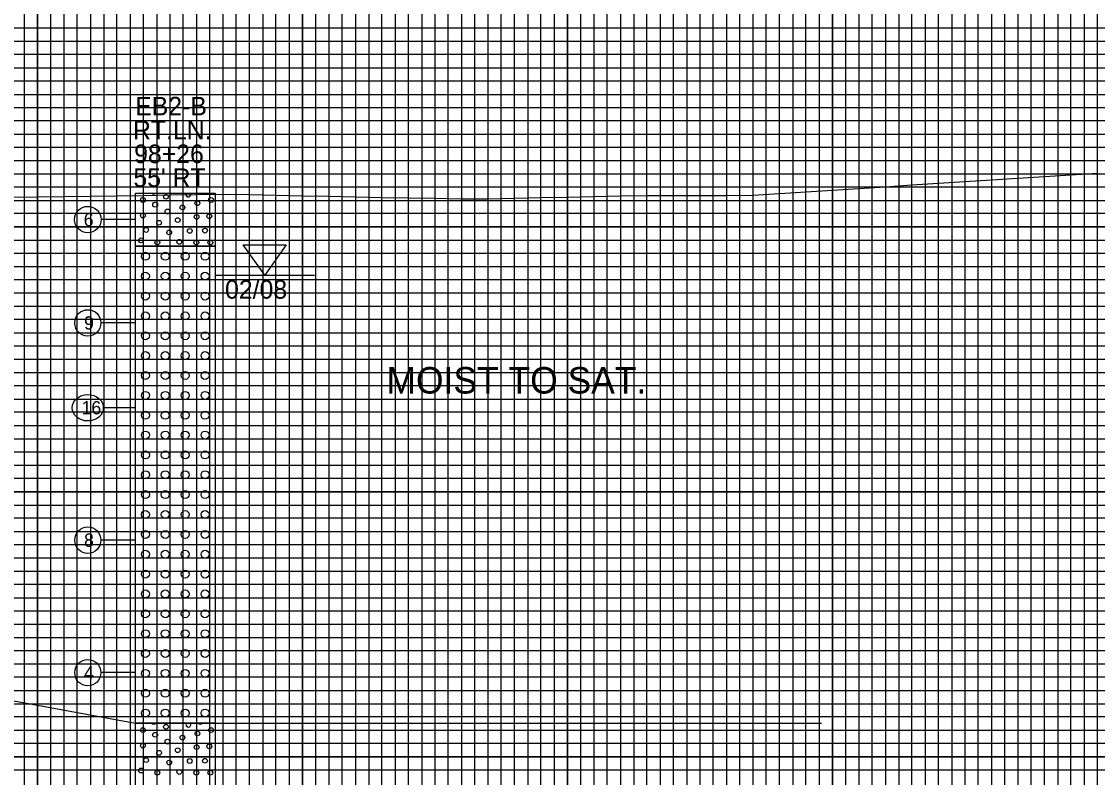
# Model space of a CAD drawing. Extents: x 2345490 to 2436403, y 465165 to 573888.
# Drawn here: x 2396213.5 to 2396619.5, y 557776.3 to 558061.6 of the extents above; entities that cross this region are included whole.
import ezdxf

# ---------------------------------------------------------------- set-up
doc = ezdxf.new("R2010")
doc.units = 0
for name, color, linetype in [('Old_Level_1', 7, 'Continuous'), ('Prop Road Sect_ Boring - Header Labels from Geopak', 7, 'Continuous'), ('Prop Road Sect_ Boring - Material (Outline)', 7, 'Continuous'), ('Prop Road Sect_ Boring - Peripheral (24 Hr GrdWtr Date)', 7, 'Continuous'), ('Prop Road Sect_ Boring - Peripheral (SPT Oval + Leader)', 7, 'Continuous'), ('Prop Road Sect_ Boring - Peripheral (SPT Tx)', 7, 'Continuous'), ('Prop Strc Sect_ Material - Contact (General - Minor)', 7, 'Continuous'), ('Prop Strc Sect_ Material - Tx (Composite Desc)', 7, 'Continuous'), ('Sheet DOT Grid CELL', 7, 'Continuous'), ('Sheet Profile Grid Major CELL', 7, 'Continuous'), ('Sheet Profile Grid Middle CELL', 7, 'Continuous'), ('Sheet Profile Grid Minor CELL', 7, 'Continuous'), ('Water Mark (24 Hr) Cell', 7, 'Continuous')]:
    doc.layers.add(name, color=color, linetype=linetype)

msp = doc.modelspace()

# ---------------------------------------------------------------- linework, layer by layer
at = {"layer": 'Old_Level_1'}
msp.add_lwpolyline([(2396209.54964, 557995.361), (2396219.54964, 557995.45925), (2396229.54964, 557995.5575), (2396239.54964, 557995.67625), (2396249.54964, 557995.834), (2396259.54964, 557995.9915), (2396269.54964, 557996.14925), (2396279.54964, 557996.30675), (2396289.54964, 557996.46425), (2396299.54964, 557996.27275), (2396309.54964, 557996.08875), (2396319.54964, 557995.85825), (2396329.54964, 557995.62925), (2396339.54964, 557995.4), (2396349.54964, 557995.2215), (2396359.54964, 557995.04825), (2396369.54964, 557994.875), (2396379.54964, 557994.70175), (2396389.54964, 557994.733), (2396399.54964, 557994.94025), (2396409.54964, 557995.1475), (2396419.54964, 557995.35475), (2396429.54964, 557995.562), (2396439.54964, 557995.76925), (2396449.54964, 557995.9055), (2396459.54964, 557995.93625), (2396469.54964, 557995.967), (2396479.54964, 557996.00175), (2396489.54964, 557996.0785), (2396499.54964, 557996.666), (2396509.54964, 557997.31575), (2396519.54964, 557997.9655), (2396529.54964, 557998.6155), (2396539.54964, 557999.26525), (2396549.54964, 557999.915), (2396559.54964, 558000.5645), (2396569.54964, 558001.192), (2396579.54964, 558001.89575), (2396589.54964, 558002.502), (2396599.54964, 558003.10825), (2396609.54964, 558003.714), (2396619.54964, 558004.3195)], dxfattribs=at)
at = {"layer": 'Prop Road Sect_ Boring - Material (Outline)'}
for points in [[(2396256.54964, 557996.83938), (2396286.54964, 557996.83938), (2396286.54964, 557976.83938), (2396256.54964, 557976.83938)], [(2396256.54964, 557976.83938), (2396286.54964, 557976.83938), (2396286.54964, 557796.83938), (2396256.54964, 557796.83938)], [(2396256.54964, 557796.83938), (2396286.54964, 557796.83938), (2396286.54964, 557596.83938), (2396256.54964, 557596.83938)]]:
    msp.add_lwpolyline(points, close=True, dxfattribs=at)
for centre, radius in [((2396268.0427, 557995.47573), 0.9), ((2396259.34269, 557994.24573), 0.9), ((2396263.9627, 557992.47573), 0.9), ((2396274.25272, 557991.44072), 0.9), ((2396279.89273, 557993.01573), 0.9), ((2396285.06774, 557994.24573), 0.9), ((2396259.34269, 557988.39572), 0.9), ((2396268.6127, 557989.89572), 0.9), ((2396279.62273, 557987.84072), 0.9), ((2396284.39274, 557988.12572), 0.9), ((2396260.55769, 557982.93571), 0.9), ((2396265.4627, 557985.66571), 0.9), ((2396272.48271, 557986.65571), 0.9), ((2396258.65268, 557979.0057), 0.9), ((2396269.27271, 557981.9907), 0.9), ((2396277.02772, 557982.59071), 0.9), ((2396282.75773, 557982.68071), 0.9), ((2396264.7727, 557978.1807), 0.9), ((2396273.08271, 557978.4507), 0.9), ((2396279.48773, 557978.1807), 0.9), ((2396284.79774, 557978.1807), 0.9), ((2396260.28653, 557972.99104), 1.5), ((2396267.78653, 557972.99104), 1.5), ((2396275.28653, 557972.99104), 1.5), ((2396282.78653, 557972.99104), 1.5), ((2396260.28653, 557965.49104), 1.5), ((2396267.78653, 557965.49104), 1.5), ((2396275.28653, 557965.49104), 1.5), ((2396282.78653, 557965.49104), 1.5), ((2396260.28653, 557957.99104), 1.5), ((2396267.78653, 557957.99104), 1.5), ((2396275.28653, 557957.99104), 1.5), ((2396282.78653, 557957.99104), 1.5), ((2396260.28653, 557950.49104), 1.5), ((2396267.78653, 557950.49104), 1.5), ((2396275.28653, 557950.49104), 1.5), ((2396282.78653, 557950.49104), 1.5), ((2396260.28653, 557943.00604), 1.5), ((2396267.78653, 557943.00604), 1.5), ((2396275.28653, 557943.00604), 1.5), ((2396282.78653, 557943.00604), 1.5), ((2396260.28653, 557935.50604), 1.5), ((2396267.78653, 557935.50604), 1.5), ((2396275.28653, 557935.50604), 1.5), ((2396282.78653, 557935.50604), 1.5), ((2396260.28653, 557928.00604), 1.5), ((2396267.78653, 557928.00604), 1.5), ((2396275.28653, 557928.00604), 1.5), ((2396282.78653, 557928.00604), 1.5), ((2396260.28653, 557920.50604), 1.5), ((2396267.78653, 557920.50604), 1.5), ((2396275.28653, 557920.50604), 1.5), ((2396282.78653, 557920.50604), 1.5), ((2396260.28653, 557913.02104), 1.5), ((2396267.78653, 557913.02104), 1.5), ((2396275.28653, 557913.02104), 1.5), ((2396282.78653, 557913.02104), 1.5), ((2396260.28653, 557905.52104), 1.5), ((2396267.78653, 557905.52104), 1.5), ((2396275.28653, 557905.52104), 1.5), ((2396282.78653, 557905.52104), 1.5), ((2396260.28653, 557898.02104), 1.5), ((2396267.78653, 557898.02104), 1.5), ((2396275.28653, 557898.02104), 1.5), ((2396282.78653, 557898.02104), 1.5), ((2396260.28653, 557890.52104), 1.5), ((2396267.78653, 557890.52104), 1.5), ((2396275.28653, 557890.52104), 1.5), ((2396282.78653, 557890.52104), 1.5), ((2396260.28653, 557883.03604), 1.5), ((2396267.78653, 557883.03604), 1.5), ((2396275.28653, 557883.03604), 1.5), ((2396282.78653, 557883.03604), 1.5), ((2396260.28653, 557875.53604), 1.5), ((2396267.78653, 557875.53604), 1.5), ((2396275.28653, 557875.53604), 1.5), ((2396282.78653, 557875.53604), 1.5), ((2396260.28653, 557868.03604), 1.5), ((2396267.78653, 557868.03604), 1.5), ((2396275.28653, 557868.03604), 1.5), ((2396282.78653, 557868.03604), 1.5), ((2396260.28653, 557860.53604), 1.5), ((2396267.78653, 557860.53604), 1.5), ((2396275.28653, 557860.53604), 1.5), ((2396282.78653, 557860.53604), 1.5), ((2396260.28653, 557853.05104), 1.5), ((2396267.78653, 557853.05104), 1.5), ((2396275.28653, 557853.05104), 1.5), ((2396282.78653, 557853.05104), 1.5), ((2396260.28653, 557845.55104), 1.5), ((2396267.78653, 557845.55104), 1.5), ((2396275.28653, 557845.55104), 1.5), ((2396282.78653, 557845.55104), 1.5), ((2396260.28653, 557838.05104), 1.5), ((2396267.78653, 557838.05104), 1.5), ((2396275.28653, 557838.05104), 1.5), ((2396282.78653, 557838.05104), 1.5), ((2396260.28653, 557830.55104), 1.5), ((2396267.78653, 557830.55104), 1.5), ((2396275.28653, 557830.55104), 1.5), ((2396282.78653, 557830.55104), 1.5), ((2396260.28653, 557823.06604), 1.5), ((2396267.78653, 557823.06604), 1.5), ((2396275.28653, 557823.06604), 1.5), ((2396282.78653, 557823.06604), 1.5), ((2396260.28653, 557815.56604), 1.5), ((2396267.78653, 557815.56604), 1.5), ((2396275.28653, 557815.56604), 1.5), ((2396282.78653, 557815.56604), 1.5), ((2396260.28653, 557808.06604), 1.5), ((2396267.78653, 557808.06604), 1.5), ((2396275.28653, 557808.06604), 1.5), ((2396282.78653, 557808.06604), 1.5), ((2396260.28653, 557800.56604), 1.5), ((2396267.78653, 557800.56604), 1.5), ((2396275.28653, 557800.56604), 1.5), ((2396282.78653, 557800.56604), 1.5), ((2396259.34269, 557794.15573), 0.9), ((2396263.9627, 557792.38573), 0.9), ((2396268.0427, 557795.38573), 0.9), ((2396279.89273, 557792.92573), 0.9), ((2396285.06774, 557794.15573), 0.9), ((2396259.34269, 557788.30572), 0.9), ((2396268.6127, 557789.80572), 0.9), ((2396274.25272, 557791.35072), 0.9), ((2396284.39274, 557788.03572), 0.9), ((2396265.4627, 557785.57571), 0.9), ((2396272.48271, 557786.56571), 0.9), ((2396279.62273, 557787.75072), 0.9), ((2396260.55769, 557782.84571), 0.9), ((2396269.27271, 557781.9007), 0.9), ((2396277.02772, 557782.50071), 0.9), ((2396282.75773, 557782.59071), 0.9), ((2396258.65268, 557778.9157), 0.9), ((2396264.7727, 557778.0907), 0.9), ((2396273.08271, 557778.3607), 0.9), ((2396279.48773, 557778.0907), 0.9), ((2396284.79774, 557778.0907), 0.9)]:
    msp.add_circle(centre, radius, dxfattribs=at)
for centre, start, end in [((2396263.42269, 557997.38074), 216.9781555, 323.0218445), ((2396276.48772, 557996.28573), 142.0367311, 37.9632689), ((2396280.98773, 557997.38074), 216.9781555, 323.0218445), ((2396263.42269, 557797.29074), 210.0999971, 329.9000029), ((2396276.48772, 557796.19573), 134.3440169, 45.6559831), ((2396280.98773, 557797.29074), 210.0999971, 329.9000029)]:
    msp.add_arc(centre, 0.9, start, end, dxfattribs=at)
at = {"layer": 'Prop Road Sect_ Boring - Peripheral (SPT Oval + Leader)'}
for p, q in [((2396256.54964, 557986.83938), (2396243.58507, 557986.83938)), ((2396256.54964, 557947.83938), (2396243.46696, 557947.83938)), ((2396256.54964, 557915.83938), (2396244.41184, 557915.83938)), ((2396256.54964, 557865.83938), (2396243.46696, 557865.83938)), ((2396256.54964, 557815.83938), (2396243.46696, 557815.83938))]:
    msp.add_line(p, q, dxfattribs=at)
for centre, major_axis, ratio in [((2396238.54964, 557986.83938), (5.03543, 0), 0.992963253), ((2396238.54964, 557947.83938), (0, 5), 0.983464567), ((2396238.54964, 557915.83938), (5.8622, 0), 0.852921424), ((2396238.54964, 557865.83938), (0, 5), 0.983464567), ((2396238.54964, 557815.83938), (0, 5), 0.983464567)]:
    msp.add_ellipse(centre, major_axis=major_axis, ratio=ratio, dxfattribs=at)
at = {"layer": 'Prop Strc Sect_ Material - Contact (General - Minor)'}
for p, q in [((2395988.54964, 557845.85303), (2396256.54964, 557796.83938)), ((2396286.54964, 557796.83938), (2396515.3748, 557796.83938))]:
    msp.add_line(p, q, dxfattribs=at)
at = {"layer": 'Sheet DOT Grid CELL'}
for p, q in [((2396219.54994, 558259.113), (2396219.54994, 557234.113)), ((2396269.54994, 558259.113), (2396269.54994, 557234.113)), ((2396319.54994, 558259.113), (2396319.54994, 557234.113)), ((2396369.54994, 558259.113), (2396369.54994, 557234.113)), ((2396419.54994, 558259.113), (2396419.54994, 557234.113)), ((2396469.54994, 558259.113), (2396469.54994, 557234.113)), ((2396519.54994, 558259.113), (2396519.54994, 557234.113)), ((2396569.54994, 558259.113), (2396569.54994, 557234.113)), ((2395319.54994, 558034.113), (2396819.54994, 558034.113)), ((2395319.54994, 557984.113), (2396819.54994, 557984.113)), ((2395319.54994, 557934.113), (2396819.54994, 557934.113)), ((2395319.54994, 557884.113), (2396819.54994, 557884.113)), ((2395319.54994, 557834.113), (2396819.54994, 557834.113)), ((2395319.54994, 557784.113), (2396819.54994, 557784.113))]:
    msp.add_line(p, q, dxfattribs=at)
at = {"layer": 'Sheet Profile Grid Major CELL'}
for points in [[(2396169.54994, 557234.113), (2396219.54994, 557234.113), (2396219.54994, 558259.113), (2396269.54994, 558259.113), (2396269.54994, 557234.113), (2396319.54994, 557234.113), (2396319.54994, 558259.113), (2396369.54994, 558259.113), (2396369.54994, 557234.113), (2396419.54994, 557234.113), (2396419.54994, 558259.113), (2396469.54994, 558259.113), (2396469.54994, 557234.113), (2396519.54994, 557234.113), (2396519.54994, 558259.113), (2396569.54994, 558259.113), (2396569.54994, 557234.113), (2396619.54994, 557234.113), (2396619.54994, 558259.113), (2396645.84994, 558259.113)], [(2396819.54994, 557984.113), (2395319.54994, 557984.113), (2395319.54994, 558034.113), (2396819.54994, 558034.113)], [(2396819.54994, 557884.113), (2395319.54994, 557884.113), (2395319.54994, 557934.113), (2396819.54994, 557934.113)], [(2396819.54994, 557784.113), (2395319.54994, 557784.113), (2395319.54994, 557834.113), (2396819.54994, 557834.113)]]:
    msp.add_lwpolyline(points, dxfattribs=at)
at = {"layer": 'Sheet Profile Grid Middle CELL'}
for points in [[(2396194.54994, 558259.113), (2396244.54994, 558259.113), (2396244.54994, 557234.113), (2396294.54994, 557234.113), (2396294.54994, 558259.113), (2396344.54994, 558259.113), (2396344.54994, 557234.113), (2396394.54994, 557234.113), (2396394.54994, 558259.113), (2396444.54994, 558259.113), (2396444.54994, 557234.113), (2396494.54994, 557234.113), (2396494.54994, 558259.113), (2396544.54994, 558259.113), (2396544.54994, 557234.113), (2396594.54994, 557234.113), (2396594.54994, 558259.113)], [(2396819.54994, 558059.113), (2395319.54994, 558059.113), (2395319.54994, 558009.113), (2396819.54994, 558009.113)], [(2396819.54994, 557959.113), (2395319.54994, 557959.113), (2395319.54994, 557909.113), (2396819.54994, 557909.113)], [(2396819.54994, 557859.113), (2395319.54994, 557859.113), (2395319.54994, 557809.113), (2396819.54994, 557809.113)]]:
    msp.add_lwpolyline(points, dxfattribs=at)
at = {"layer": 'Sheet Profile Grid Minor CELL'}
msp.add_line((2396769.54994, 558054.113), (2395369.54994, 558054.113), dxfattribs=at)
for points in [[(2396209.54994, 558259.113), (2396214.54994, 558259.113), (2396214.54994, 557234.113)], [(2396224.54994, 557234.113), (2396224.54994, 558259.113), (2396229.54994, 558259.113), (2396229.54994, 557234.113)], [(2396234.54994, 557234.113), (2396234.54994, 558259.113), (2396239.54994, 558259.113), (2396239.54994, 557234.113)], [(2396249.54994, 557234.113), (2396249.54994, 558259.113), (2396254.54994, 558259.113), (2396254.54994, 557234.113)], [(2396259.54994, 557234.113), (2396259.54994, 558259.113), (2396264.54994, 558259.113), (2396264.54994, 557234.113)], [(2396274.54994, 557234.113), (2396274.54994, 558259.113), (2396279.54994, 558259.113), (2396279.54994, 557234.113)], [(2396284.54994, 557234.113), (2396284.54994, 558259.113), (2396289.54994, 558259.113), (2396289.54994, 557234.113)], [(2396299.54994, 557234.113), (2396299.54994, 558259.113), (2396304.54994, 558259.113), (2396304.54994, 557234.113)], [(2396309.54994, 557234.113), (2396309.54994, 558259.113), (2396314.54994, 558259.113), (2396314.54994, 557234.113)], [(2396324.54994, 557234.113), (2396324.54994, 558259.113), (2396329.54994, 558259.113), (2396329.54994, 557234.113)], [(2396334.54994, 557234.113), (2396334.54994, 558259.113), (2396339.54994, 558259.113), (2396339.54994, 557234.113)], [(2396349.54994, 557234.113), (2396349.54994, 558259.113), (2396354.54994, 558259.113), (2396354.54994, 557234.113)], [(2396359.54994, 557234.113), (2396359.54994, 558259.113), (2396364.54994, 558259.113), (2396364.54994, 557234.113)], [(2396374.54994, 557234.113), (2396374.54994, 558259.113), (2396379.54994, 558259.113), (2396379.54994, 557234.113)], [(2396384.54994, 557234.113), (2396384.54994, 558259.113), (2396389.54994, 558259.113), (2396389.54994, 557234.113)], [(2396399.54994, 557234.113), (2396399.54994, 558259.113), (2396404.54994, 558259.113), (2396404.54994, 557234.113)], [(2396409.54994, 557234.113), (2396409.54994, 558259.113), (2396414.54994, 558259.113), (2396414.54994, 557234.113)], [(2396424.54994, 557234.113), (2396424.54994, 558259.113), (2396429.54994, 558259.113), (2396429.54994, 557234.113)], [(2396434.54994, 557234.113), (2396434.54994, 558259.113), (2396439.54994, 558259.113), (2396439.54994, 557234.113)], [(2396449.54994, 557234.113), (2396449.54994, 558259.113), (2396454.54994, 558259.113), (2396454.54994, 557234.113)], [(2396459.54994, 557234.113), (2396459.54994, 558259.113), (2396464.54994, 558259.113), (2396464.54994, 557234.113)], [(2396474.54994, 557234.113), (2396474.54994, 558259.113), (2396479.54994, 558259.113), (2396479.54994, 557234.113)], [(2396484.54994, 557234.113), (2396484.54994, 558259.113), (2396489.54994, 558259.113), (2396489.54994, 557234.113)], [(2396499.54994, 557234.113), (2396499.54994, 558259.113), (2396504.54994, 558259.113), (2396504.54994, 557234.113)], [(2396509.54994, 557234.113), (2396509.54994, 558259.113), (2396514.54994, 558259.113), (2396514.54994, 557234.113)], [(2396524.54994, 557234.113), (2396524.54994, 558259.113), (2396529.54994, 558259.113), (2396529.54994, 557234.113)], [(2396534.54994, 557234.113), (2396534.54994, 558259.113), (2396539.54994, 558259.113), (2396539.54994, 557234.113)], [(2396549.54994, 557234.113), (2396549.54994, 558259.113), (2396554.54994, 558259.113), (2396554.54994, 557234.113)], [(2396559.54994, 557234.113), (2396559.54994, 558259.113), (2396564.54994, 558259.113), (2396564.54994, 557234.113)], [(2396574.54994, 557234.113), (2396574.54994, 558259.113), (2396579.54994, 558259.113), (2396579.54994, 557234.113)], [(2396584.54994, 557234.113), (2396584.54994, 558259.113), (2396589.54994, 558259.113), (2396589.54994, 557234.113)], [(2396599.54994, 557234.113), (2396599.54994, 558259.113), (2396604.54994, 558259.113), (2396604.54994, 557234.113)], [(2396609.54994, 557234.113), (2396609.54994, 558259.113), (2396614.54994, 558259.113), (2396614.54994, 557234.113)], [(2396769.54994, 558049.113), (2395369.54994, 558049.113), (2395369.54994, 558044.113), (2396769.54994, 558044.113)], [(2396769.54994, 558039.113), (2395369.54994, 558039.113)], [(2395369.54994, 558029.113), (2396769.54994, 558029.113)], [(2396769.54994, 558024.113), (2395369.54994, 558024.113), (2395369.54994, 558019.113), (2396769.54994, 558019.113)], [(2396769.54994, 558014.113), (2395369.54994, 558014.113), (2395369.54994, 558004.113), (2396769.54994, 558004.113)], [(2396769.54994, 557999.113), (2395369.54994, 557999.113), (2395369.54994, 557994.113), (2396769.54994, 557994.113)], [(2396769.54994, 557989.113), (2395369.54994, 557989.113), (2395369.54994, 557979.113), (2396769.54994, 557979.113)], [(2396769.54994, 557974.113), (2395369.54994, 557974.113), (2395369.54994, 557969.113), (2396769.54994, 557969.113)], [(2396769.54994, 557964.113), (2395369.54994, 557964.113), (2395369.54994, 557954.113), (2396769.54994, 557954.113)], [(2396769.54994, 557949.113), (2395369.54994, 557949.113), (2395369.54994, 557944.113), (2396769.54994, 557944.113)], [(2396769.54994, 557939.113), (2395369.54994, 557939.113), (2395369.54994, 557929.113), (2396769.54994, 557929.113)], [(2396769.54994, 557924.113), (2395369.54994, 557924.113), (2395369.54994, 557919.113), (2396769.54994, 557919.113)], [(2396769.54994, 557914.113), (2395369.54994, 557914.113), (2395369.54994, 557904.113), (2396769.54994, 557904.113)], [(2396769.54994, 557899.113), (2395369.54994, 557899.113), (2395369.54994, 557894.113), (2396769.54994, 557894.113)], [(2396769.54994, 557889.113), (2395369.54994, 557889.113), (2395369.54994, 557879.113), (2396769.54994, 557879.113)], [(2396769.54994, 557874.113), (2395369.54994, 557874.113), (2395369.54994, 557869.113), (2396769.54994, 557869.113)], [(2396769.54994, 557864.113), (2395369.54994, 557864.113), (2395369.54994, 557854.113), (2396769.54994, 557854.113)], [(2396769.54994, 557849.113), (2395369.54994, 557849.113), (2395369.54994, 557844.113), (2396769.54994, 557844.113)], [(2396769.54994, 557839.113), (2395369.54994, 557839.113), (2395369.54994, 557829.113), (2396769.54994, 557829.113)], [(2396769.54994, 557824.113), (2395369.54994, 557824.113), (2395369.54994, 557819.113), (2396769.54994, 557819.113)], [(2396769.54994, 557814.113), (2395369.54994, 557814.113), (2395369.54994, 557804.113), (2396769.54994, 557804.113)], [(2396769.54994, 557799.113), (2395369.54994, 557799.113), (2395369.54994, 557794.113), (2396769.54994, 557794.113)], [(2396769.54994, 557789.113), (2395369.54994, 557789.113), (2395369.54994, 557779.113), (2396769.54994, 557779.113)]]:
    msp.add_lwpolyline(points, dxfattribs=at)
at = {"layer": 'Water Mark (24 Hr) Cell'}
for p, q in [((2396286.54964, 557965.83938), (2396305.29964, 557965.83938)), ((2396305.29964, 557965.83938), (2396324.04964, 557965.83938))]:
    msp.add_line(p, q, dxfattribs=at)
msp.add_lwpolyline([(2396297.23714, 557977.37063), (2396313.36214, 557977.37063), (2396305.29964, 557965.83938)], close=True, dxfattribs=at)

# ---------------------------------------------------------------- texts
at = {"layer": 'Prop Road Sect_ Boring - Header Labels from Geopak'}
for s, p in [('EB2-B', (2396256.42466, 558026.17903)), ('RT.LN.', (2396255.59789, 558017.17903)), ('98+26', (2396256.03884, 558008.17903)), ("55' RT", (2396255.76325, 557999.17903))]:
    msp.add_text(s, height=7, dxfattribs=at).set_placement(p)
at = {"layer": 'Prop Road Sect_ Boring - Peripheral (24 Hr GrdWtr Date)'}
msp.add_text('02/08', height=7, dxfattribs=at).set_placement((2396290.34669, 557957.00451))
at = {"layer": 'Prop Road Sect_ Boring - Peripheral (SPT Tx)'}
for s, p in [('6', (2396237.01421, 557984.33938)), ('9', (2396237.13232, 557945.33938)), ('16', (2396236.18744, 557913.33938)), ('8', (2396237.13232, 557863.33938)), ('4', (2396237.13232, 557813.33938))]:
    msp.add_text(s, height=5, dxfattribs=at).set_placement(p)
at = {"layer": 'Prop Strc Sect_ Material - Tx (Composite Desc)'}
msp.add_text('MOIST TO SAT.', height=10, dxfattribs=at).set_placement((2396351.25259, 557921.1906))

doc.saveas('drawing.dxf')
